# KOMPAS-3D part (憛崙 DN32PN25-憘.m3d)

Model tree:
1. Объединить компоненты:1  (labels: СЕНС DN32PN25)
2. Эскиз:1
3. Операция выдавливания:1
     Расстояние 1 = 14
4. Фаска:1
     Угол = 45; Длина 1 = 2; Длина 2 = 2

Referenced files in D:\Савин\!СЕНСОР\3D для заказчика\!Новый перечень\СЕНС\1. СЕНС\DN32\: СЕНС DN32PN25.a3d
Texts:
  СЕНС DN32PN25-СВ
  ООО НПП Сенсор
  СЕНС DN32PN25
